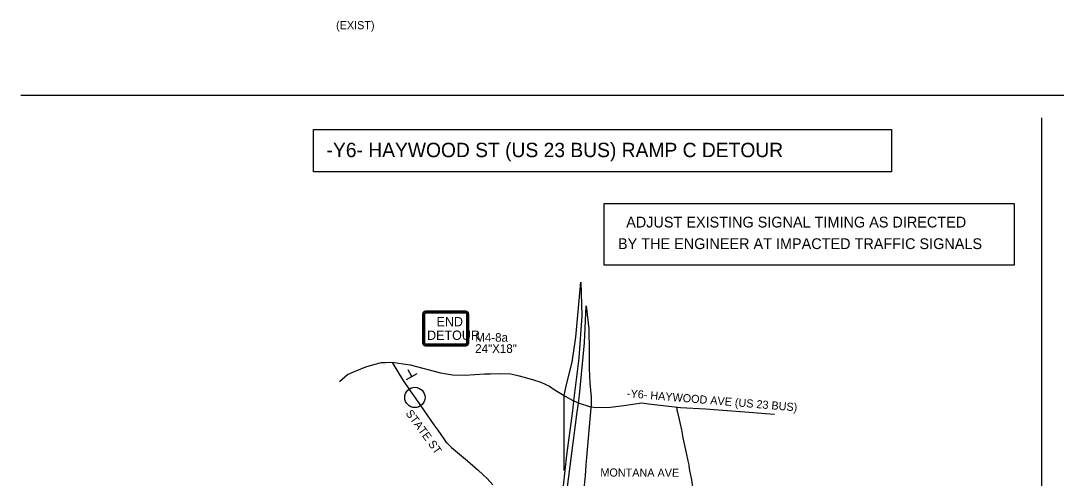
# Model space of a CAD drawing. Extents: x 886234 to 968767, y 455416 to 684046.
# Drawn here: x 904674 to 919066, y 483857 to 490219 of the extents above; entities that cross this region are included whole.
import ezdxf

# ---------------------------------------------------------------- set-up
doc = ezdxf.new("R2010")
doc.units = 0
for name, color, linetype in [('Scratch_Level_3', 7, 'Continuous'), ('TC DEV SIGN', 7, 'Continuous'), ('TC DEV SIGN BLACK ZERO', 7, 'Continuous'), ('TC DEV SIGN ORANGE', 7, 'Continuous'), ('TC LABEL TEXT', 7, 'Continuous')]:
    doc.layers.add(name, color=color, linetype=linetype)

msp = doc.modelspace()

# ---------------------------------------------------------------- linework, layer by layer
at = {"layer": 'Scratch_Level_3'}
msp.add_line((904674, 489183), (936553, 489183), dxfattribs=at)
at = {"layer": 'TC DEV SIGN'}
for p, q in [((910034, 485233), (910183, 485312)), ((910108, 485272), (910059, 485365))]:
    msp.add_line(p, q, dxfattribs=at)
at = {"layer": 'TC DEV SIGN BLACK ZERO'}
for p, q in [((910860, 486180), (910300, 486180)), ((910300, 486179), (910300, 486179)), ((910860, 486179), (910300, 486179)), ((910860, 486170), (910300, 486170)), ((910860, 486179), (910860, 486179)), ((910260, 486140), (910260, 485740)), ((910262, 486140), (910262, 485740)), ((910262, 486140), (910262, 486140)), ((910270, 486140), (910270, 485740)), ((910287, 486140), (910287, 485740)), ((910860, 486154), (910300, 486154)), ((910873, 485740), (910873, 486140)), ((910890, 485740), (910890, 486140)), ((910898, 486140), (910898, 486140)), ((910898, 485740), (910898, 486140)), ((910900, 485740), (910900, 486140)), ((910262, 485740), (910262, 485740)), ((910898, 485740), (910898, 485740)), ((910300, 485710), (910300, 485727)), ((910300, 485727), (910860, 485727)), ((910300, 485727), (910300, 485710)), ((910300, 485710), (910860, 485710)), ((910300, 485700), (910300, 485702)), ((910300, 485702), (910300, 485702)), ((910300, 485702), (910860, 485702)), ((910300, 485702), (910300, 485700)), ((910300, 485700), (910860, 485700)), ((910860, 485702), (910860, 485702))]:
    msp.add_line(p, q, dxfattribs=at)
for centre, major_axis, start_param, end_param in [((910300, 486140), (40, 0), 1.570796, 3.141593), ((910300, 486140), (38.3, 0), 1.570796, 3.141593), ((910300, 486140), (30, 0), 1.570796, 3.141593), ((910860, 486140), (40, 0), 0, 1.570796), ((910860, 486140), (38.3, 0), 0, 1.570796), ((910860, 486140), (30, 0), 0, 1.570796), ((910300, 486140), (13.3, 0), 1.570796, 3.141593), ((910860, 486140), (13.3, 0), 0, 1.570796), ((910300, 485740), (40, 0), 3.141593, 4.712389), ((910300, 485740), (38.3, 0), 3.141593, 4.712389), ((910300, 485740), (30, 0), 3.141593, 4.712389), ((910300, 485740), (13.3, 0), 3.141593, 4.712389), ((910860, 485740), (30, 0), 4.712389, 6.283185), ((910860, 485740), (13.3, 0), 4.712389, 6.283185), ((910860, 485740), (40, 0), 4.712389, 6.283185), ((910860, 485740), (38.3, 0), 4.712389, 6.283185)]:
    msp.add_ellipse(centre, major_axis=major_axis, ratio=0.999865, start_param=start_param, end_param=end_param, dxfattribs=at)
at = {"layer": 'TC DEV SIGN ORANGE'}
for p, q in [((910860, 486180), (910300, 486180)), ((910260, 486140), (910260, 485740)), ((910900, 485740), (910900, 486140)), ((910300, 485700), (910860, 485700))]:
    msp.add_line(p, q, dxfattribs=at)
for centre, start_param, end_param in [((910300, 486140), 1.570796, 3.141593), ((910860, 486140), 0, 1.570796), ((910300, 485740), 3.141593, 4.712389), ((910860, 485740), 4.712389, 6.283185)]:
    msp.add_ellipse(centre, major_axis=(40, 0), ratio=0.999865, start_param=start_param, end_param=end_param, dxfattribs=at)
at = {"layer": 'TC LABEL TEXT'}
msp.add_line((918864, 475460), (918864, 488867), dxfattribs=at)
for points in [[(908742, 488707), (916777, 488707), (916777, 488116), (908742, 488116)], [(912783, 487678), (918479, 487678), (918479, 486819), (912783, 486819)]]:
    msp.add_lwpolyline(points, close=True, dxfattribs=at)
for points in [[(912228, 485007), (912258, 485160), (912340, 485473), (912388, 485820), (912458, 486585)], [(912458, 486585), (912473, 486121), (912429, 485526), (912358, 484936)], [(912426, 484903), (912438, 485013), (912511, 485739), (912532, 486253)], [(912532, 486253), (912570, 485935), (912574, 485625), (912574, 485383), (912583, 485179), (912600, 484984), (912604, 484848)], [(909103, 485202), (909218, 485298), (909314, 485344), (909469, 485409), (909581, 485439), (909689, 485465), (909745, 485469), (909830, 485470), (910087, 485433), (910509, 485325), (910677, 485295), (910850, 485289), (911121, 485309), (911205, 485309), (911349, 485316), (911485, 485310), (911601, 485283), (911785, 485231), (911902, 485193), (912021, 485136), (912086, 485092), (912182, 485034), (912239, 484998), (912358, 484936)], [(909838, 485469), (909981, 485233), (910089, 485074)], [(910089, 485074), (910211, 484895), (910280, 484796)], [(911322, 481383), (911388, 481558), (911447, 481675), (911515, 481793), (911588, 481906), (911780, 482170), (911929, 482428), (912066, 482737), (912148, 482984), (912191, 483172), (912238, 483450), (912401, 484743), (912426, 484903)], [(912358, 484936), (912341, 484793), (912258, 484181), (912211, 483751), (912175, 483540), (912160, 483410), (912089, 483043), (912022, 482837), (911898, 482514)], [(912228, 483965), (912228, 484747), (912228, 484859), (912228, 485007)], [(912358, 484936), (912392, 484920), (912426, 484903)], [(915150, 484744), (915023, 484754), (914858, 484768), (914190, 484817), (913844, 484837), (913399, 484890), (913308, 484902), (913056, 484864), (912869, 484841), (912683, 484838), (912596, 484847), (912426, 484903)], [(910280, 484796), (910417, 484600), (910470, 484524), (910562, 484390), (910589, 484355), (910595, 484348)], [(912597, 484837), (912539, 484152)], [(913787, 484844), (913791, 484822), (913794, 484810), (913800, 484775), (913833, 484633), (913857, 484533), (913877, 484419), (913899, 484314), (913923, 484209), (913947, 484098), (913960, 484042), (913961, 484029)], [(910595, 484348), (910660, 484286), (910882, 484099), (911030, 483969), (911095, 483911), (911156, 483852), (911234, 483765)], [(912539, 484152), (912530, 484040), (912517, 483894), (912506, 483758), (912490, 483622), (912481, 483528), (912479, 483495)], [(913961, 484029), (913971, 483964), (913996, 483837), (914016, 483706), (914037, 483595), (914059, 483474), (914075, 483380), (914080, 483356)]]:
    msp.add_lwpolyline(points, dxfattribs=at)
msp.add_circle((910152, 484981), 141, dxfattribs=at)
msp.add_circle((910152, 484981), 141, dxfattribs=at)

# ---------------------------------------------------------------- texts
at = {"layer": 'TC DEV SIGN BLACK ZERO'}
for s, height, p in [('END', 130, (910454, 485970)), ('DETOUR', 130, (910322, 485781)), ('M4-8a', 120, (910991, 485756)), ('24"X18"', 120, (910991, 485601))]:
    msp.add_text(s, height=height, rotation=360, dxfattribs=at).set_placement(p)
at = {"layer": 'TC LABEL TEXT'}
for s, height, p in [('(EXIST)', 112.5, (909057, 490101)), ('-Y6- HAYWOOD ST (US 23 BUS) RAMP C DETOUR', 200, (908925, 488322)), ('ADJUST EXISTING SIGNAL TIMING AS DIRECTED', 150, (913089, 487344)), ('BY THE ENGINEER AT IMPACTED TRAFFIC SIGNALS', 150, (912975, 487044))]:
    msp.add_text(s, height=height, dxfattribs=at).set_placement(p)
for s, rotation, p in [('-Y6- HAYWOOD AVE (US 23 BUS)', 355.2398, (913096, 484984)), ('STATE ST', 306.1918, (910018, 484760)), ('MONTANA AVE', 359.7628, (912730, 483882))]:
    msp.add_text(s, height=112.5, rotation=rotation, dxfattribs=at).set_placement(p)

doc.saveas('drawing.dxf')
